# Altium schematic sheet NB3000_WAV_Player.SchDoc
size B; Organization: Altium Limited; Address1: L3, 12a Rodborough Rd; Address2: Frenchs Forest; Address3: NSW; Address4: Australia 2086; DocumentNumber: 1; SheetNumber: 1; SheetTotal: 2
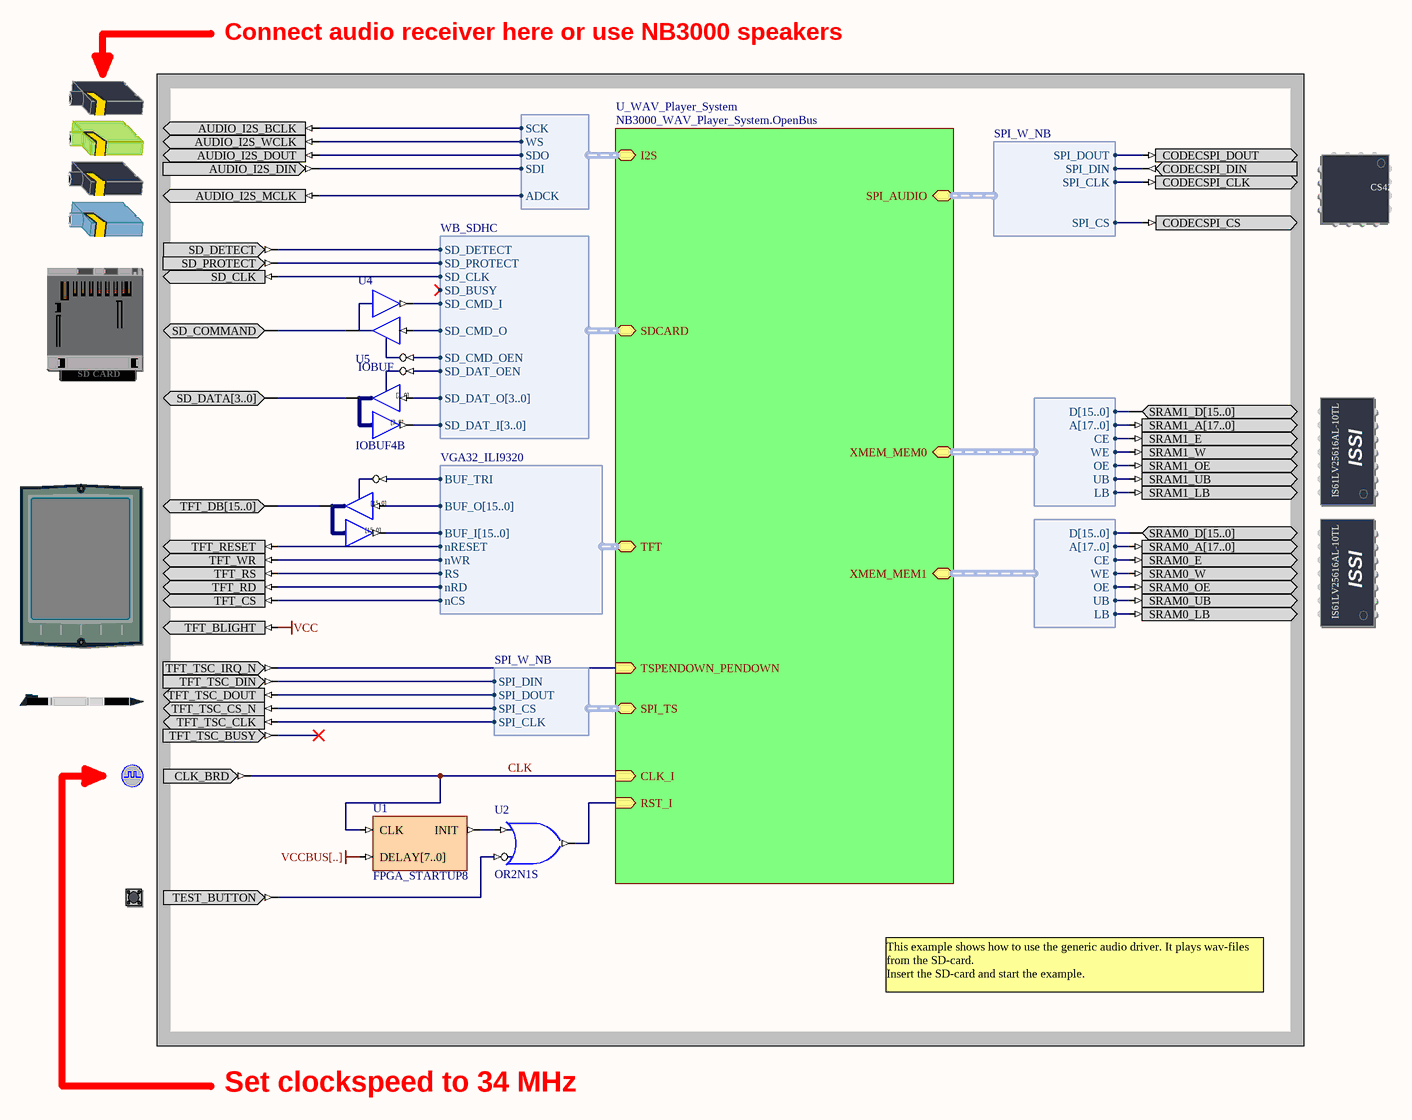
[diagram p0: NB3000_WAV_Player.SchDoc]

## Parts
(Parts that share a designator on the sheet are numbered #1, #2 ... from top to bottom, then left to right.)
?#1  AUDIO_CODEC  (value not drawn)
?#2  AUDIO_CODEC_CTRL  (value not drawn)
?#3  SD_HOST  (value not drawn)
?#4  SRAM1  (value not drawn)
?#5  TFT_LCD  (value not drawn)
?#6  SRAM0  (value not drawn)
?#7  TFT_PEN  (value not drawn)
?#8  CLOCK_BOARD  (value not drawn)
?#9  TEST_BUTTON  (value not drawn)
U1  FPGA_STARTUP8
U2  OR2N1S
U3  IOBUF16B  (value not drawn)
U4  IOBUF
U5  IOBUF4B

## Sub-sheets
U_WAV_Player_System = NB3000_WAV_Player_System.OpenBus: CLK_I (in), RST_I (in), I2S (harness I2S_W_Both), XMEM_MEM0 (harness WB_MEM_CTRL_SRAM16_A18), XMEM_MEM1 (harness WB_MEM_CTRL_SRAM16_A18), TSPENDOWN_PENDOWN (in), TFT (harness VGA32_ILI9320), SPI_AUDIO (harness SPI_W_NB), SDCARD (harness WB_SDHC), SPI_TS (harness SPI_W_NB)

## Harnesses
I2S_W_Both: SCK, WS, SDO, SDI, ADCK
WB_MEM_CTRL_SRAM16_A18: D[15..0], A[17..0], CE, WE, OE, UB, LB
VGA32_ILI9320: BUF_TRI, BUF_O[15..0], BUF_I[15..0], nRESET, nWR, RS, nRD, nCS
SPI_W_NB: SPI_DOUT, SPI_DIN, SPI_CLK, SPI_CS
WB_SDHC: SD_DETECT, SD_PROTECT, SD_CLK, SD_BUSY, SD_CMD_OEN, SD_CMD_O, SD_CMD_I, SD_DAT_OEN, SD_DAT_O[3..0], SD_DAT_I[3..0]

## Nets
VCC: ?#5.TFT_BLIGHT
VCCBUS[..]: U1.DELAY[7..0]
CLK: ?#8.CLK_BRD U1.CLK ; sheet U_WAV_Player_System/CLK_I
Net?#1_AUDIO_I2S_BCLK: ?#1.AUDIO_I2S_BCLK ; sheet U_WAV_Player_System/I2S.SCK
Net?#1_AUDIO_I2S_DIN: ?#1.AUDIO_I2S_DIN ; sheet U_WAV_Player_System/I2S.SDI
Net?#1_AUDIO_I2S_DOUT: ?#1.AUDIO_I2S_DOUT ; sheet U_WAV_Player_System/I2S.SDO
Net?#1_AUDIO_I2S_MCLK: ?#1.AUDIO_I2S_MCLK ; sheet U_WAV_Player_System/I2S.ADCK
Net?#1_AUDIO_I2S_WCLK: ?#1.AUDIO_I2S_WCLK ; sheet U_WAV_Player_System/I2S.WS
Net?#2_CODECSPI_CLK: ?#2.CODECSPI_CLK ; sheet U_WAV_Player_System/SPI_AUDIO.SPI_CLK
Net?#2_CODECSPI_CS: ?#2.CODECSPI_CS ; sheet U_WAV_Player_System/SPI_AUDIO.SPI_CS
Net?#2_CODECSPI_DIN: ?#2.CODECSPI_DIN ; sheet U_WAV_Player_System/SPI_AUDIO.SPI_DIN
Net?#2_CODECSPI_DOUT: ?#2.CODECSPI_DOUT ; sheet U_WAV_Player_System/SPI_AUDIO.SPI_DOUT
Net?#3_SD_CLK: ?#3.SD_CLK ; sheet U_WAV_Player_System/SDCARD.SD_CLK
Net?#3_SD_COMMAND: ?#3.SD_COMMAND U4.IO
Net?#3_SD_DETECT: ?#3.SD_DETECT ; sheet U_WAV_Player_System/SDCARD.SD_DETECT
Net?#3_SD_PROTECT: ?#3.SD_PROTECT ; sheet U_WAV_Player_System/SDCARD.SD_PROTECT
Net?#4_SRAM1_E: ?#4.SRAM1_E ; sheet U_WAV_Player_System/XMEM_MEM0.CE
Net?#4_SRAM1_LB: ?#4.SRAM1_LB ; sheet U_WAV_Player_System/XMEM_MEM0.LB
Net?#4_SRAM1_OE: ?#4.SRAM1_OE ; sheet U_WAV_Player_System/XMEM_MEM0.OE
Net?#4_SRAM1_UB: ?#4.SRAM1_UB ; sheet U_WAV_Player_System/XMEM_MEM0.UB
Net?#4_SRAM1_W: ?#4.SRAM1_W ; sheet U_WAV_Player_System/XMEM_MEM0.WE
Net?#5_TFT_CS: ?#5.TFT_CS ; sheet U_WAV_Player_System/TFT.nCS
Net?#5_TFT_RD: ?#5.TFT_RD ; sheet U_WAV_Player_System/TFT.nRD
Net?#5_TFT_RESET: ?#5.TFT_RESET ; sheet U_WAV_Player_System/TFT.nRESET
Net?#5_TFT_RS: ?#5.TFT_RS ; sheet U_WAV_Player_System/TFT.RS
Net?#5_TFT_WR: ?#5.TFT_WR ; sheet U_WAV_Player_System/TFT.nWR
Net?#6_SRAM0_E: ?#6.SRAM0_E ; sheet U_WAV_Player_System/XMEM_MEM1.CE
Net?#6_SRAM0_LB: ?#6.SRAM0_LB ; sheet U_WAV_Player_System/XMEM_MEM1.LB
Net?#6_SRAM0_OE: ?#6.SRAM0_OE ; sheet U_WAV_Player_System/XMEM_MEM1.OE
Net?#6_SRAM0_UB: ?#6.SRAM0_UB ; sheet U_WAV_Player_System/XMEM_MEM1.UB
Net?#6_SRAM0_W: ?#6.SRAM0_W ; sheet U_WAV_Player_System/XMEM_MEM1.WE
Net?#7_TFT_TSC_CLK: ?#7.TFT_TSC_CLK ; sheet U_WAV_Player_System/SPI_TS.SPI_CLK
Net?#7_TFT_TSC_CS_N: ?#7.TFT_TSC_CS_N ; sheet U_WAV_Player_System/SPI_TS.SPI_CS
Net?#7_TFT_TSC_DIN: ?#7.TFT_TSC_DIN ; sheet U_WAV_Player_System/SPI_TS.SPI_DIN
Net?#7_TFT_TSC_DOUT: ?#7.TFT_TSC_DOUT ; sheet U_WAV_Player_System/SPI_TS.SPI_DOUT
Net?#7_TFT_TSC_IRQ_N: ?#7.TFT_TSC_IRQ_N ; sheet U_WAV_Player_System/TSPENDOWN_PENDOWN
Net?#9_TEST_BUTTON: ?#9.TEST_BUTTON U2.I0
NetU1_INIT: U1.INIT U2.I1
NetU2_O: U2.O ; sheet U_WAV_Player_System/RST_I
NetU3_T: U3.T ; sheet U_WAV_Player_System/TFT.BUF_TRI
NetU4_I: U4.I ; sheet U_WAV_Player_System/SDCARD.SD_CMD_O
NetU4_O: U4.O ; sheet U_WAV_Player_System/SDCARD.SD_CMD_I
NetU4_T: U4.T ; sheet U_WAV_Player_System/SDCARD.SD_CMD_OEN
NetU5_T: U5.T ; sheet U_WAV_Player_System/SDCARD.SD_DAT_OEN

Not connected (* = marked no-connect by the designer): ?#3 SD_DATA[3..0]; ?#4 SRAM1_A[17..0] SRAM1_D[15..0]; ?#5 TFT_DB[15..0]; ?#6 SRAM0_A[17..0] SRAM0_D[15..0]; ?#7 TFT_TSC_BUSY*; U3 I[15..0] IO[15..0] O[15..0]; U5 I[3..0] IO[3..0] O[3..0]

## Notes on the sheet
- Connect audio receiver here or use NB3000 speakers
- This example shows how to use the generic audio driver. It plays wav-files from the SD-card.
  Insert the SD-card and start the example.
- Set clockspeed to 34 MHz

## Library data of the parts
?#1 = AUDIO_CODEC: Audio Codec; PortComponent: True; IncludeInDSF: AUDIO_CS4270
?#2 = AUDIO_CODEC_CTRL: Audio Codec Control; PortComponent: True
?#3 = SD_HOST: Secure Digital Card Host; PortComponent: True
?#4 = SRAM1: Free Static RAM - Daughterboard; PortComponent: True
?#5 = TFT_LCD: TFT LCD Panel; PortComponent: True
?#6 = SRAM0: Free Static RAM - Daughterboard; PortComponent: True
?#7 = TFT_PEN: Touch Screen Pen Control; PortComponent: True
?#8 = CLOCK_BOARD: Global System Clock Supply; PortComponent: True
?#9 = TEST_BUTTON: Test / Reset Button; PortComponent: True
U1 = FPGA_STARTUP8: FPGA Startup With 8 Bit Delay
U2 = OR2N1S: 2-Input OR Gate with Active Low A Input, Single Pin Version; XilinxEquivalent: OR2B1; FunctionalClass: Logic Primitive; PortSize: 2; ArchiveName: GENERIC; VHDLIB_SIM: GENERIC_LIB
U3 = IOBUF16B: 16-Bit Input/Output Buffer, Bus Version; SubClass: IOBUF; Enable: Low; Control: Common Control T; PortSize: 16; ArchiveName: GENERIC; VHDLIB_SIM: GENERIC_LIB
U4 = IOBUF: Input/Output Buffer; Enable: Low; Control: Common Control T; ArchiveName: GENERIC; VHDLIB_SIM: GENERIC_LIB
U5 = IOBUF4B: 4-Bit Input/Output Buffer, Bus Version; SubClass: IOBUF; Enable: Low; Control: Common Control T; PortSize: 4; ArchiveName: GENERIC; VHDLIB_SIM: GENERIC_LIB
